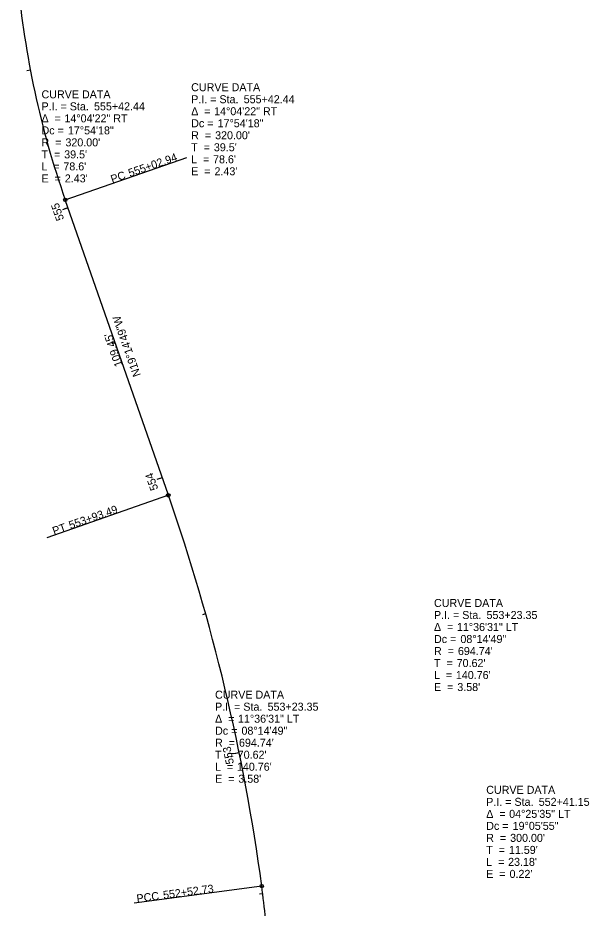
# Model space of a CAD drawing. Extents: x 1922787 to 1923078, y 359089 to 360354.
# Drawn here: x 1922844.2 to 1923044.1, y 359724.2 to 360035.7 of the extents above; entities that cross this region are included whole.
import ezdxf

# ---------------------------------------------------------------- set-up
doc = ezdxf.new("R2010")
doc.units = 0
for name, color, linetype in [('GE_P_Alignment', 7, 'Continuous'), ('GE_P_Alignment_1000_Curve_Data', 7, 'Continuous'), ('GE_P_Alignment_1000_Stations', 7, 'Continuous'), ('GE_P_Alignment_100_Curve_Data', 7, 'Continuous'), ('GE_P_Alignment_100_Stations', 7, 'Continuous'), ('GE_P_Alignment_500_Curve_Data', 7, 'Continuous'), ('GE_P_Alignment_500_Stations', 7, 'Continuous')]:
    doc.layers.add(name, color=color, linetype=linetype)

msp = doc.modelspace()

# ---------------------------------------------------------------- linework, layer by layer
at = {"layer": 'GE_P_Alignment'}
msp.add_line((1922896.9, 359868.63), (1922860.82, 359971.97), dxfattribs=at)
for centre, radius, start, end in [((1923162.93, 360077.45), 320, 185.1742, 199.2469), ((1922240.99, 359639.62), 694.74, 7.63833, 19.24694), ((1922632.22, 359692.09), 300, 3.2119, 7.6383)]:
    msp.add_arc(centre, radius, start, end, dxfattribs=at)
at = {"layer": 'GE_P_Alignment_1000_Stations'}
for p, q in [((1922860.82, 359971.97), (1922903.3, 359986.8)), ((1922861.79, 359969.19), (1922860.65, 359968.8)), ((1922896.9, 359868.63), (1922854.41, 359853.8)), ((1922929.56, 359731.96), (1922884.96, 359725.98))]:
    msp.add_line(p, q, dxfattribs=at)
for centre in [(1922860.82, 359971.97), (1922896.9, 359868.63), (1922929.56, 359731.96)]:
    msp.add_circle(centre, 0.6, dxfattribs=at)
at = {"layer": 'GE_P_Alignment_100_Stations'}
for p, q in [((1922848.62, 360017.38), (1922847.44, 360017.15)), ((1922860.82, 359971.97), (1922903.3, 359986.8)), ((1922861.79, 359969.19), (1922859.9, 359968.53)), ((1922878.27, 359921.99), (1922877.13, 359921.59)), ((1922894.75, 359874.78), (1922892.86, 359874.12)), ((1922896.9, 359868.63), (1922854.41, 359853.8)), ((1922909.94, 359827.15), (1922908.78, 359826.83)), ((1922921.69, 359778.57), (1922919.73, 359778.17)), ((1922929.56, 359731.96), (1922884.96, 359725.98)), ((1922929.91, 359729.26), (1922928.72, 359729.11))]:
    msp.add_line(p, q, dxfattribs=at)
for centre in [(1922860.82, 359971.97), (1922896.9, 359868.63), (1922929.56, 359731.96)]:
    msp.add_circle(centre, 0.6, dxfattribs=at)
at = {"layer": 'GE_P_Alignment_500_Stations'}
for p, q in [((1922860.82, 359971.97), (1922903.3, 359986.8)), ((1922861.79, 359969.19), (1922859.9, 359968.53)), ((1922894.75, 359874.78), (1922893.62, 359874.39)), ((1922896.9, 359868.63), (1922854.41, 359853.8)), ((1922921.69, 359778.57), (1922920.52, 359778.33)), ((1922929.56, 359731.96), (1922884.96, 359725.98))]:
    msp.add_line(p, q, dxfattribs=at)
for centre in [(1922860.82, 359971.97), (1922896.9, 359868.63), (1922929.56, 359731.96)]:
    msp.add_circle(centre, 0.6, dxfattribs=at)

# ---------------------------------------------------------------- texts
at = {"layer": 'GE_P_Alignment_1000_Curve_Data'}
for s, p in [('CURVE DATA', (1922852.53, 360007.48)), ('P.I. = Sta. ', (1922852.53, 360003.28)), ('555+42.44', (1922870.89, 360003.28)), ('Δ  = ', (1922852.53, 359999.08)), ('14°04\'22" RT', (1922860.55, 359999.08)), ('Dc = ', (1922852.53, 359994.88)), ('17°54\'18"', (1922861.76, 359994.88)), ('R  = ', (1922852.53, 359990.68)), ("320.00'", (1922860.89, 359990.68)), ('T  = ', (1922852.53, 359986.48)), ("39.5'", (1922860.46, 359986.48)), ('L  = ', (1922852.53, 359982.28)), ("78.6'", (1922860.17, 359982.28)), ('E  = ', (1922852.53, 359978.08)), ("2.43'", (1922860.68, 359978.08)), ('CURVE DATA', (1922913.23, 359797.5)), ('P.I. = Sta. ', (1922913.23, 359793.3)), ('553+23.35', (1922931.6, 359793.3)), ('Δ  = ', (1922913.23, 359789.1)), ('11°36\'31" LT', (1922921.25, 359789.1)), ('Dc = ', (1922913.23, 359784.9)), ('08°14\'49"', (1922922.47, 359784.9)), ('R  = ', (1922913.23, 359780.7)), ("694.74'", (1922921.6, 359780.7)), ('T  = ', (1922913.23, 359776.5)), ("70.62'", (1922921.16, 359776.5)), ('L  = ', (1922913.23, 359772.3)), ("140.76'", (1922920.88, 359772.3)), ('E  = ', (1922913.23, 359768.1)), ("3.58'", (1922921.38, 359768.1))]:
    msp.add_text(s, height=2.8, dxfattribs=at).set_placement(p)
for s, p in [('N19°14\'49"W', (1922887.3, 359910.68)), ("109.45'", (1922880.95, 359914.16))]:
    msp.add_text(s, height=2.8, rotation=109.2469, dxfattribs=at).set_placement(p)
at = {"layer": 'GE_P_Alignment_1000_Stations'}
for s, rotation, p in [('555+02.94', 19.2469, (1922883.45, 359979.92)), ('PC', 19.2469, (1922877.29, 359977.77)), ('553+93.49', 19.2469, (1922862.66, 359856.73)), ('PT', 19.2469, (1922856.92, 359854.72)), ('552+52.73', 7.6383, (1922895.24, 359727.41)), ('PCC', 7.6383, (1922885.97, 359726.17))]:
    msp.add_text(s, height=2.8, rotation=rotation, dxfattribs=at).set_placement(p)
at = {"layer": 'GE_P_Alignment_100_Curve_Data'}
for s, p in [('CURVE DATA', (1922904.88, 360009.97)), ('P.I. = Sta. ', (1922904.88, 360005.77)), ('555+42.44', (1922923.25, 360005.77)), ('Δ  = ', (1922904.88, 360001.57)), ('14°04\'22" RT', (1922912.91, 360001.57)), ('Dc = ', (1922904.88, 359997.37)), ('17°54\'18"', (1922914.12, 359997.37)), ('R  = ', (1922904.88, 359993.17)), ("320.00'", (1922913.25, 359993.17)), ('T  = ', (1922904.88, 359988.97)), ("39.5'", (1922912.82, 359988.97)), ('L  = ', (1922904.88, 359984.77)), ("78.6'", (1922912.53, 359984.77)), ('E  = ', (1922904.88, 359980.57)), ("2.43'", (1922913.04, 359980.57)), ('CURVE DATA', (1922989.81, 359829.57)), ('P.I. = Sta. ', (1922989.81, 359825.37)), ('553+23.35', (1923008.18, 359825.37)), ('Δ  = ', (1922989.81, 359821.17)), ('11°36\'31" LT', (1922997.83, 359821.17)), ('Dc = ', (1922989.81, 359816.97)), ('08°14\'49"', (1922999.05, 359816.97)), ('R  = ', (1922989.81, 359812.77)), ("694.74'", (1922998.18, 359812.77)), ('T  = ', (1922989.81, 359808.57)), ("70.62'", (1922997.74, 359808.57)), ('L  = ', (1922989.81, 359804.37)), ("140.76'", (1922997.46, 359804.37)), ('E  = ', (1922989.81, 359800.17)), ("3.58'", (1922997.96, 359800.17)), ('CURVE DATA', (1923008.08, 359764.22)), ('P.I. = Sta. ', (1923008.08, 359760.02)), ('552+41.15', (1923026.45, 359760.02)), ('Δ  = ', (1923008.08, 359755.82)), ('04°25\'35" LT', (1923016.11, 359755.82)), ('Dc = ', (1923008.08, 359751.62)), ('19°05\'55"', (1923017.32, 359751.62)), ("300.00'", (1923016.45, 359747.42)), ('R  = ', (1923008.08, 359747.42)), ('T  = ', (1923008.08, 359743.22)), ("11.59'", (1923016.02, 359743.22)), ('L  = ', (1923008.08, 359739.02)), ("23.18'", (1923015.73, 359739.02)), ('E  = ', (1923008.08, 359734.82)), ("0.22'", (1923016.24, 359734.82))]:
    msp.add_text(s, height=2.8, dxfattribs=at).set_placement(p)
for s, p in [('N19°14\'49"W', (1922887.3, 359910.68)), ("109.45'", (1922880.95, 359914.16))]:
    msp.add_text(s, height=2.8, rotation=109.2469, dxfattribs=at).set_placement(p)
at = {"layer": 'GE_P_Alignment_100_Stations'}
for s, rotation, p in [('555+02.94', 19.2469, (1922883.45, 359979.92)), ('PC', 19.2469, (1922877.29, 359977.77)), ('555', 109.2469, (1922860.47, 359965.24)), ('554', 109.2469, (1922893.41, 359870.88)), ('553+93.49', 19.2469, (1922862.66, 359856.73)), ('PT', 19.2469, (1922856.92, 359854.72)), ('553', 101.5369, (1922919.85, 359774.86)), ('552+52.73', 7.6383, (1922895.24, 359727.41)), ('PCC', 7.6383, (1922885.97, 359726.17))]:
    msp.add_text(s, height=2.8, rotation=rotation, dxfattribs=at).set_placement(p)
at = {"layer": 'GE_P_Alignment_500_Curve_Data'}
for s, p in [('CURVE DATA', (1922852.53, 360007.48)), ('P.I. = Sta. ', (1922852.53, 360003.28)), ('555+42.44', (1922870.89, 360003.28)), ('Δ  = ', (1922852.53, 359999.08)), ('14°04\'22" RT', (1922860.55, 359999.08)), ('Dc = ', (1922852.53, 359994.88)), ('17°54\'18"', (1922861.76, 359994.88)), ('R  = ', (1922852.53, 359990.68)), ("320.00'", (1922860.89, 359990.68)), ('T  = ', (1922852.53, 359986.48)), ("39.5'", (1922860.46, 359986.48)), ('L  = ', (1922852.53, 359982.28)), ("78.6'", (1922860.17, 359982.28)), ('E  = ', (1922852.53, 359978.08)), ("2.43'", (1922860.68, 359978.08)), ('CURVE DATA', (1922913.23, 359797.5)), ('P.I. = Sta. ', (1922913.23, 359793.3)), ('553+23.35', (1922931.6, 359793.3)), ('Δ  = ', (1922913.23, 359789.1)), ('11°36\'31" LT', (1922921.25, 359789.1)), ('Dc = ', (1922913.23, 359784.9)), ('08°14\'49"', (1922922.47, 359784.9)), ('R  = ', (1922913.23, 359780.7)), ("694.74'", (1922921.6, 359780.7)), ('T  = ', (1922913.23, 359776.5)), ("70.62'", (1922921.16, 359776.5)), ('L  = ', (1922913.23, 359772.3)), ("140.76'", (1922920.88, 359772.3)), ('E  = ', (1922913.23, 359768.1)), ("3.58'", (1922921.38, 359768.1))]:
    msp.add_text(s, height=2.8, dxfattribs=at).set_placement(p)
for s, p in [('N19°14\'49"W', (1922887.3, 359910.68)), ("109.45'", (1922880.95, 359914.16))]:
    msp.add_text(s, height=2.8, rotation=109.2469, dxfattribs=at).set_placement(p)
at = {"layer": 'GE_P_Alignment_500_Stations'}
for s, rotation, p in [('555+02.94', 19.2469, (1922883.45, 359979.92)), ('PC', 19.2469, (1922877.29, 359977.77)), ('555', 109.2469, (1922860.47, 359965.24)), ('553+93.49', 19.2469, (1922862.66, 359856.73)), ('PT', 19.2469, (1922856.92, 359854.72)), ('552+52.73', 7.6383, (1922895.24, 359727.41)), ('PCC', 7.6383, (1922885.97, 359726.17))]:
    msp.add_text(s, height=2.8, rotation=rotation, dxfattribs=at).set_placement(p)

doc.saveas('drawing.dxf')
